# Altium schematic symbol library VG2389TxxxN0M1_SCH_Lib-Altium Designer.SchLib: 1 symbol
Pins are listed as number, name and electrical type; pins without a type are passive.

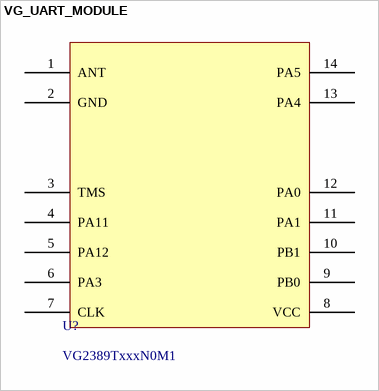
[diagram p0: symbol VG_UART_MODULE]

## VG_UART_MODULE
designator U?, comment VG2389TxxxN0M1
footprint VG_UART_MODULE
footprint VG_UART_MODULE-TO
footprint VG_UART_MODULE-TP
footprint VG_UART_MODULE-TO-TEST
pins: 1 ANT, 2 GND, 3 TMS, 4 PA11, 5 PA12, 6 PA3, 7 CLK, 8 VCC, 9 PB0, 10 PB1, 11 PA1, 12 PA0, 13 PA4, 14 PA5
